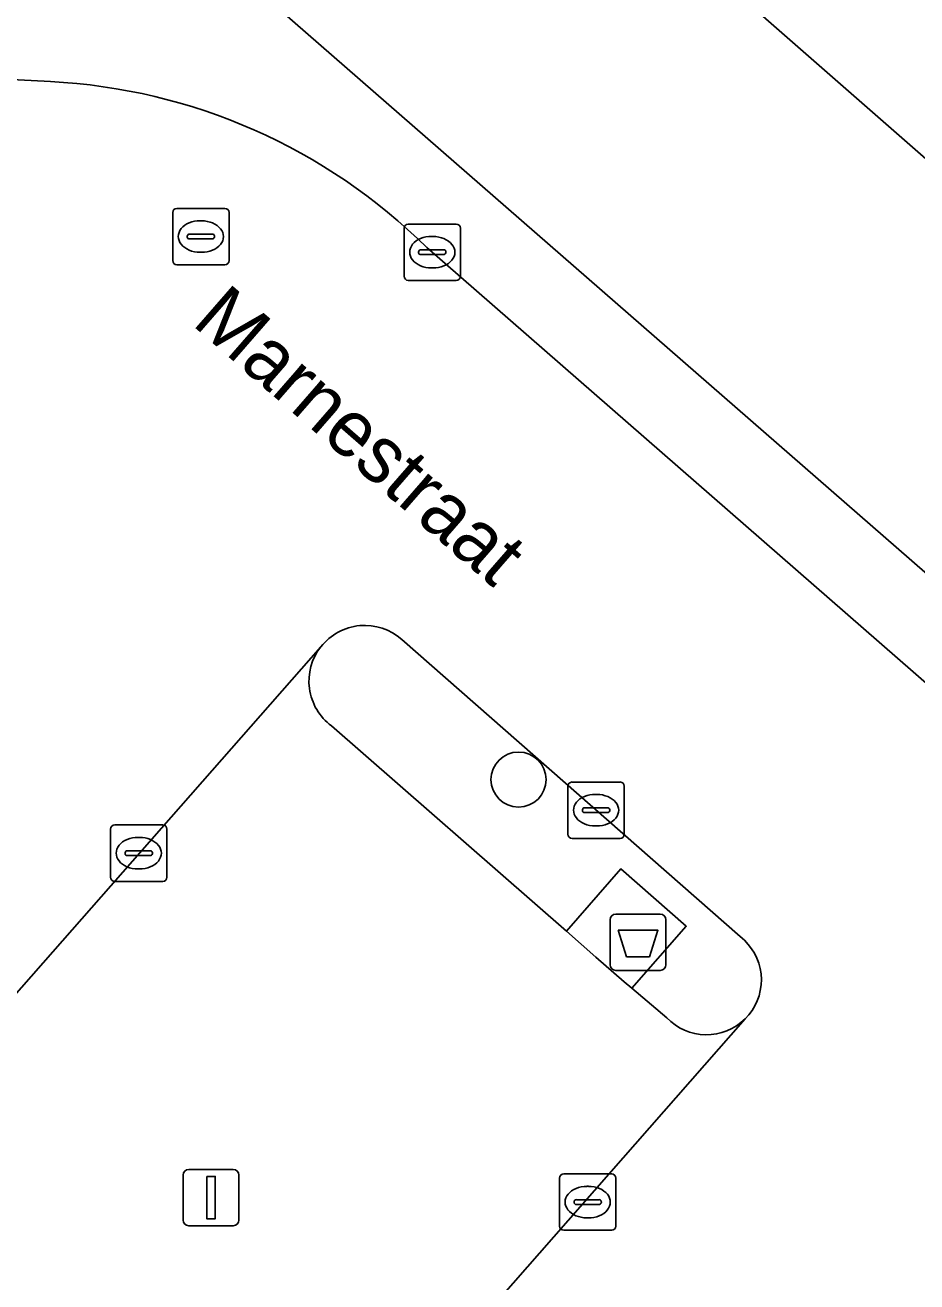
# Model space of a CAD drawing. Extents: x 158472 to 159562, y 388525 to 389606.
# Drawn here: x 158695 to 158710.83, y 388787.63 to 388809.93 of the extents above; entities that cross this region are included whole.
import ezdxf

# ---------------------------------------------------------------- set-up
doc = ezdxf.new("R2010")
doc.units = 0
for name, color, linetype in [('IMGEO_Afval_apart_plaats', 7, 'Continuous'), ('IMGEO_Boom', 7, 'Continuous'), ('IMGEO_Erf', 7, 'Continuous'), ('IMGEO_Kolk', 7, 'Continuous'), ('IMGEO_Lichtmast', 7, 'Continuous'), ('IMGEO_Openbare_ruimte_label', 7, 'Continuous'), ('IMGEO_Pand', 7, 'Continuous'), ('IMGEO_Parkeervlak_open', 7, 'Continuous'), ('IMGEO_Rijbaan_lokaal_open', 7, 'Continuous'), ('IMGEO_Rioolput', 7, 'Continuous'), ('IMGEO_Verkeerseiland_open', 7, 'Continuous'), ('IMGEO_Voetpad_gesloten', 7, 'Continuous'), ('IMGEO_Voetpad_open', 7, 'Continuous')]:
    doc.layers.add(name, color=color, linetype=linetype)

msp = doc.modelspace()

# ---------------------------------------------------------------- linework, layer by layer
at = {"layer": 'IMGEO_Afval_apart_plaats'}
for p, q in [((158705.388, 388793.255), (158705.388, 388794.055)), ((158705.388, 388794.055), (158705.388, 388793.255)), ((158705.488, 388794.155), (158706.278, 388794.155)), ((158706.278, 388794.155), (158705.488, 388794.155)), ((158706.378, 388794.055), (158706.378, 388793.255)), ((158706.378, 388793.255), (158706.378, 388794.055)), ((158706.278, 388793.155), (158705.488, 388793.155)), ((158705.488, 388793.155), (158706.278, 388793.155))]:
    msp.add_line(p, q, dxfattribs=at)
msp.add_lwpolyline([(158705.531, 388793.869), (158706.235, 388793.869), (158706.086, 388793.399), (158705.68, 388793.399), (158705.531, 388793.869)], dxfattribs=at)
for centre, start, end in [((158705.488, 388794.055), 90, 180), ((158705.488, 388794.055), 90, 180), ((158706.278, 388794.055), 0, 90), ((158706.278, 388794.055), 360, 90), ((158705.488, 388793.255), 180, 270), ((158705.488, 388793.255), 180, 270), ((158706.278, 388793.255), 270, 0), ((158706.278, 388793.255), 270, 0)]:
    msp.add_arc(centre, 0.1, start, end, dxfattribs=at)
at = {"layer": 'IMGEO_Boom'}
msp.add_circle((158703.762, 388796.542), 0.489, dxfattribs=at)
at = {"layer": 'IMGEO_Erf'}
for points in [[(158755.409, 388834.448), (158755.525, 388834.58), (158744.162, 388844.524), (158717.279, 388843.045), (158714.843, 388878.448), (158710.585, 388882.112), (158711.768, 388864.623), (158712.592, 388851.925), (158713.284, 388842.825), (158695.563, 388822.552), (158691.151, 388817.503), (158723.402, 388789.393), (158732.269, 388781.671)], [(158739.458, 388782.374), (158743.881, 388787.434), (158750.795, 388795.344), (158772.286, 388819.929), (158768.141, 388823.539), (158746.61, 388798.883), (158746.441, 388798.69), (158748.638, 388796.764), (158745.763, 388793.485), (158743.368, 388795.584), (158746.243, 388798.864), (158737.995, 388806.093), (158727.335, 388793.947), (158731.344, 388790.539), (158729.417, 388788.062), (158725.407, 388791.603), (158726.994, 388793.559), (158726.792, 388793.735), (158698.095, 388818.851), (158709.148, 388831.481), (158733.85, 388809.893), (158755.409, 388834.448)]]:
    msp.add_lwpolyline(points, dxfattribs=at)
at = {"layer": 'IMGEO_Kolk'}
for p, q in [((158701.73, 388805.476), (158701.73, 388806.328)), ((158701.805, 388806.402), (158702.657, 388806.402)), ((158702.731, 388806.328), (158702.731, 388805.476)), ((158702.218, 388806.182), (158702.243, 388806.182)), ((158701.989, 388805.896), (158701.989, 388805.908)), ((158702.427, 388805.859), (158702.029, 388805.859)), ((158702.032, 388805.945), (158702.43, 388805.945)), ((158702.473, 388805.908), (158702.473, 388805.896)), ((158702.241, 388805.622), (158702.216, 388805.622)), ((158702.657, 388805.402), (158701.805, 388805.402)), ((158704.713, 388796.499), (158705.565, 388796.499)), ((158704.638, 388795.573), (158704.638, 388796.425)), ((158705.126, 388796.279), (158705.151, 388796.279)), ((158705.639, 388796.425), (158705.639, 388795.573)), ((158704.897, 388795.993), (158704.897, 388796.005)), ((158704.94, 388796.042), (158705.338, 388796.042)), ((158705.381, 388796.005), (158705.381, 388795.993)), ((158705.335, 388795.956), (158704.937, 388795.956)), ((158696.52, 388794.81), (158696.52, 388795.662)), ((158696.595, 388795.736), (158697.447, 388795.736)), ((158697.521, 388795.662), (158697.521, 388794.81)), ((158705.149, 388795.719), (158705.124, 388795.719)), ((158697.008, 388795.516), (158697.033, 388795.516)), ((158705.565, 388795.499), (158704.713, 388795.499)), ((158696.779, 388795.23), (158696.779, 388795.242)), ((158697.217, 388795.193), (158696.819, 388795.193)), ((158696.822, 388795.279), (158697.22, 388795.279)), ((158697.263, 388795.242), (158697.263, 388795.23)), ((158697.031, 388794.956), (158697.006, 388794.956)), ((158697.447, 388794.736), (158696.595, 388794.736)), ((158704.564, 388789.543), (158705.416, 388789.543)), ((158704.489, 388788.617), (158704.489, 388789.469)), ((158704.977, 388789.323), (158705.002, 388789.323)), ((158705.49, 388789.469), (158705.49, 388788.617)), ((158704.748, 388789.037), (158704.748, 388789.049)), ((158705.186, 388789), (158704.788, 388789)), ((158704.791, 388789.086), (158705.189, 388789.086)), ((158705.232, 388789.049), (158705.232, 388789.037)), ((158705, 388788.763), (158704.975, 388788.763)), ((158705.416, 388788.543), (158704.564, 388788.543))]:
    msp.add_line(p, q, dxfattribs=at)
for points in [[(158701.73, 388805.476), (158701.73, 388806.328)], [(158701.805, 388806.402), (158702.657, 388806.402)], [(158702.731, 388806.328), (158702.731, 388805.476)], [(158702.657, 388805.402), (158701.805, 388805.402)], [(158704.713, 388796.499), (158705.565, 388796.499)], [(158704.638, 388795.573), (158704.638, 388796.425)], [(158705.639, 388796.425), (158705.639, 388795.573)], [(158696.52, 388794.81), (158696.52, 388795.662)], [(158696.595, 388795.736), (158697.447, 388795.736)], [(158697.521, 388795.662), (158697.521, 388794.81)], [(158705.565, 388795.499), (158704.713, 388795.499)], [(158697.447, 388794.736), (158696.595, 388794.736)], [(158704.564, 388789.543), (158705.416, 388789.543)], [(158704.489, 388788.617), (158704.489, 388789.469)], [(158705.49, 388789.469), (158705.49, 388788.617)], [(158705.416, 388788.543), (158704.564, 388788.543)]]:
    msp.add_lwpolyline(points, dxfattribs=at)
for centre, radius, start, end in [((158701.807, 388806.326), 0.0765, 91.552, 178.448), ((158701.807, 388806.326), 0.0765, 91.552, 178.448), ((158702.655, 388806.326), 0.0765, 1.552, 88.448), ((158702.655, 388806.326), 0.0765, 1.552, 88.448), ((158702.029, 388805.905), 0.0403, 85.8775, 175.7526), ((158702.026, 388805.895), 0.0366, 178.938, 274.7102), ((158702.43, 388805.902), 0.043, 264.8664, 352.4533), ((158702.434, 388805.907), 0.0386, 1.7309, 96.639), ((158701.807, 388805.478), 0.0765, 181.552, 268.448), ((158701.807, 388805.478), 0.0765, 181.552, 268.448), ((158702.655, 388805.478), 0.0765, 271.552, 358.448), ((158702.655, 388805.478), 0.0765, 271.552, 358.448), ((158704.715, 388796.423), 0.0765, 91.552, 178.448), ((158704.715, 388796.423), 0.0765, 91.552, 178.448), ((158705.563, 388796.423), 0.0765, 1.552, 88.448), ((158705.563, 388796.423), 0.0765, 1.552, 88.448), ((158704.937, 388796.002), 0.0403, 85.8775, 175.7526), ((158705.342, 388796.004), 0.0386, 1.7309, 96.639), ((158704.934, 388795.992), 0.0366, 178.938, 274.7102), ((158705.338, 388795.999), 0.043, 264.8664, 352.4533), ((158696.597, 388795.66), 0.0765, 91.552, 178.448), ((158696.597, 388795.66), 0.0765, 91.552, 178.448), ((158697.445, 388795.66), 0.0765, 1.552, 88.448), ((158697.445, 388795.66), 0.0765, 1.552, 88.448), ((158704.715, 388795.575), 0.0765, 181.552, 268.448), ((158704.715, 388795.575), 0.0765, 181.552, 268.448), ((158705.563, 388795.575), 0.0765, 271.552, 358.448), ((158705.563, 388795.575), 0.0765, 271.552, 358.448), ((158696.819, 388795.239), 0.0403, 85.8775, 175.7526), ((158696.816, 388795.229), 0.0366, 178.938, 274.7102), ((158697.22, 388795.236), 0.043, 264.8664, 352.4533), ((158697.224, 388795.241), 0.0386, 1.7309, 96.639), ((158696.597, 388794.812), 0.0765, 181.552, 268.448), ((158696.597, 388794.812), 0.0765, 181.552, 268.448), ((158697.445, 388794.812), 0.0765, 271.552, 358.448), ((158697.445, 388794.812), 0.0765, 271.552, 358.448), ((158704.566, 388789.467), 0.0765, 91.552, 178.448), ((158704.566, 388789.467), 0.0765, 91.552, 178.448), ((158705.414, 388789.467), 0.0765, 1.552, 88.448), ((158705.414, 388789.467), 0.0765, 1.552, 88.448), ((158704.788, 388789.046), 0.0403, 85.8775, 175.7526), ((158704.785, 388789.036), 0.0366, 178.938, 274.7102), ((158705.189, 388789.043), 0.043, 264.8664, 352.4533), ((158705.193, 388789.048), 0.0386, 1.7309, 96.639), ((158704.566, 388788.619), 0.0765, 181.552, 268.448), ((158704.566, 388788.619), 0.0765, 181.552, 268.448), ((158705.414, 388788.619), 0.0765, 271.552, 358.448), ((158705.414, 388788.619), 0.0765, 271.552, 358.448)]:
    msp.add_arc(centre, radius, start, end, dxfattribs=at)
for centre, major_axis, ratio, start_param, end_param in [((158702.217, 388805.902), (-0.387, 0.002), 0.722429, 4.712389, 7.853982), ((158702.242, 388805.902), (-0.39, 0.002), 0.717154, 1.570796, 4.712389), ((158705.125, 388795.999), (-0.387, 0.002), 0.722429, 4.712389, 7.853982), ((158705.15, 388795.999), (-0.39, 0.002), 0.717154, 1.570796, 4.712389), ((158697.007, 388795.236), (-0.387, 0.002), 0.722429, 4.712389, 7.853982), ((158697.032, 388795.236), (-0.39, 0.002), 0.717154, 1.570796, 4.712389), ((158704.976, 388789.043), (-0.387, 0.002), 0.722429, 4.712389, 7.853982), ((158705.001, 388789.043), (-0.39, 0.002), 0.717154, 1.570796, 4.712389)]:
    msp.add_ellipse(centre, major_axis=major_axis, ratio=ratio, start_param=start_param, end_param=end_param, dxfattribs=at)
at = {"layer": 'IMGEO_Lichtmast'}
for p, q in [((158697.909, 388789.623), (158698.699, 388789.623)), ((158698.699, 388789.623), (158697.909, 388789.623)), ((158697.809, 388788.723), (158697.809, 388789.523)), ((158697.809, 388789.523), (158697.809, 388788.723)), ((158698.799, 388789.523), (158698.799, 388788.723)), ((158698.799, 388788.723), (158698.799, 388789.523)), ((158698.699, 388788.623), (158697.909, 388788.623)), ((158697.909, 388788.623), (158698.699, 388788.623))]:
    msp.add_line(p, q, dxfattribs=at)
msp.add_lwpolyline([(158698.229, 388789.498), (158698.379, 388789.498), (158698.379, 388788.748), (158698.229, 388788.748), (158698.229, 388789.498)], dxfattribs=at)
for centre, start, end in [((158697.909, 388789.523), 90, 180), ((158697.909, 388789.523), 90, 180), ((158698.699, 388789.523), 0, 90), ((158698.699, 388789.523), 360, 90), ((158697.909, 388788.723), 180, 270), ((158697.909, 388788.723), 180, 270), ((158698.699, 388788.723), 270, 0), ((158698.699, 388788.723), 270, 0)]:
    msp.add_arc(centre, 0.1, start, end, dxfattribs=at)
at = {"layer": 'IMGEO_Pand'}
msp.add_lwpolyline([(158709.148, 388831.481), (158698.095, 388818.851), (158726.792, 388793.735), (158726.994, 388793.559), (158727.335, 388793.947), (158737.995, 388806.093), (158733.85, 388809.893)], close=True, dxfattribs=at)
at = {"layer": 'IMGEO_Parkeervlak_open'}
for points in [[(158700.254, 388798.9), (158687.175, 388784.023), (158693.219, 388775.707), (158707.784, 388792.295)], [(158706.393, 388792.313), (158705.775, 388792.837), (158705.639, 388792.953), (158705.137, 388793.391), (158704.612, 388793.851), (158700.442, 388797.495)]]:
    msp.add_lwpolyline(points, dxfattribs=at)
for centre, radius, start, end in [((158701.03, 388798.289), 0.988, 141.7908, 233.4519), ((158707.097, 388792.986), 0.974, 223.7097, 314.8075)]:
    msp.add_arc(centre, radius, start, end, dxfattribs=at)
at = {"layer": 'IMGEO_Rijbaan_lokaal_open'}
for points in [[(158695.453, 388808.93), (158687.154, 388809.359)], [(158732.078, 388779.858), (158722.415, 388788.289), (158702.136, 388805.983)], [(158701.688, 388799.027), (158707.698, 388793.755), (158707.774, 388793.689)], [(158684.139, 388788.199), (158687.175, 388784.023), (158700.254, 388798.9)], [(158707.784, 388792.295), (158693.219, 388775.707), (158693.274, 388775.631), (158695.007, 388773.247), (158696.814, 388770.761), (158711.638, 388787.571), (158712.353, 388788.381)]]:
    msp.add_lwpolyline(points, dxfattribs=at)
for centre, radius, start, end in [((158694.936, 388798.707), 10.236, 45.3016, 87.1064), ((158701.031, 388798.291), 0.987, 48.2247, 141.8975), ((158707.096, 388792.987), 0.976, 314.81, 46.0121)]:
    msp.add_arc(centre, radius, start, end, dxfattribs=at)
at = {"layer": 'IMGEO_Rioolput'}
for p, q in [((158697.623, 388805.754), (158697.623, 388806.606)), ((158697.698, 388806.68), (158698.55, 388806.68)), ((158698.624, 388806.606), (158698.624, 388805.754)), ((158698.111, 388806.46), (158698.136, 388806.46)), ((158697.882, 388806.174), (158697.882, 388806.186)), ((158698.32, 388806.137), (158697.922, 388806.137)), ((158697.925, 388806.223), (158698.323, 388806.223)), ((158698.366, 388806.186), (158698.366, 388806.174)), ((158698.134, 388805.9), (158698.109, 388805.9)), ((158698.55, 388805.68), (158697.698, 388805.68))]:
    msp.add_line(p, q, dxfattribs=at)
for points in [[(158697.623, 388805.754), (158697.623, 388806.606)], [(158697.698, 388806.68), (158698.55, 388806.68)], [(158698.624, 388806.606), (158698.624, 388805.754)], [(158698.55, 388805.68), (158697.698, 388805.68)]]:
    msp.add_lwpolyline(points, dxfattribs=at)
for centre, radius, start, end in [((158697.7, 388806.604), 0.0765, 91.552, 178.448), ((158697.7, 388806.604), 0.0765, 91.552, 178.448), ((158698.548, 388806.604), 0.0765, 1.552, 88.448), ((158698.548, 388806.604), 0.0765, 1.552, 88.448), ((158697.922, 388806.183), 0.0403, 85.8775, 175.7526), ((158697.919, 388806.173), 0.0366, 178.938, 274.7102), ((158698.323, 388806.18), 0.043, 264.8664, 352.4533), ((158698.327, 388806.185), 0.0386, 1.7309, 96.639), ((158697.7, 388805.756), 0.0765, 181.552, 268.448), ((158697.7, 388805.756), 0.0765, 181.552, 268.448), ((158698.548, 388805.756), 0.0765, 271.552, 358.448), ((158698.548, 388805.756), 0.0765, 271.552, 358.448)]:
    msp.add_arc(centre, radius, start, end, dxfattribs=at)
for centre, major_axis, ratio, start_param, end_param in [((158698.11, 388806.18), (-0.387, 0.002), 0.722429, 4.712389, 7.853982), ((158698.135, 388806.18), (-0.39, 0.002), 0.717154, 1.570796, 4.712389)]:
    msp.add_ellipse(centre, major_axis=major_axis, ratio=ratio, start_param=start_param, end_param=end_param, dxfattribs=at)
at = {"layer": 'IMGEO_Verkeerseiland_open'}
for points in [[(158707.774, 388793.689), (158707.698, 388793.755), (158701.688, 388799.027)], [(158700.442, 388797.495), (158704.612, 388793.851), (158705.577, 388794.955), (158706.739, 388793.94), (158705.775, 388792.837), (158706.393, 388792.313)]]:
    msp.add_lwpolyline(points, dxfattribs=at)
for centre, radius, start, end in [((158701.031, 388798.291), 0.987, 48.2247, 141.8975), ((158701.03, 388798.289), 0.988, 141.7908, 233.4519), ((158707.096, 388792.987), 0.976, 314.81, 46.0121), ((158707.097, 388792.986), 0.974, 223.7097, 314.8075)]:
    msp.add_arc(centre, radius, start, end, dxfattribs=at)
at = {"layer": 'IMGEO_Voetpad_gesloten'}
msp.add_lwpolyline([(158704.612, 388793.851), (158705.137, 388793.391), (158705.639, 388792.953), (158705.775, 388792.837), (158706.739, 388793.94), (158705.577, 388794.955)], close=True, dxfattribs=at)
at = {"layer": 'IMGEO_Voetpad_open'}
for points in [[(158702.136, 388805.983), (158722.415, 388788.289), (158723.402, 388789.393), (158691.151, 388817.503)], [(158687.154, 388809.359), (158695.453, 388808.93)]]:
    msp.add_lwpolyline(points, dxfattribs=at)
msp.add_arc((158694.936, 388798.707), 10.236, 45.3016, 87.1064, dxfattribs=at)

# ---------------------------------------------------------------- texts
at = {"layer": 'IMGEO_Openbare_ruimte_label'}
msp.add_text('Marnestraat', height=1, rotation=318.9326, dxfattribs=at).set_placement((158697.944, 388804.626))

doc.saveas('drawing.dxf')
